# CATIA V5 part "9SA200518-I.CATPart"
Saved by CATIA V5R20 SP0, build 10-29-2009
Part number: 9SA200518-I
Revision: ANY
Definition: UNKNOWN
Nomenclature: 9SA200518-I
Source: Unknown
Bounding box of the stored display mesh (mm): x -5.752 to 5.752, y -16 to 3, z -5.9 to 5.9
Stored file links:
  C:\Users\Utente\Desktop\IO LAVORO\3D X SITO CF\CUMSA\3D files SA\SA 200518\9SA200518-I.CATPart
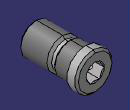
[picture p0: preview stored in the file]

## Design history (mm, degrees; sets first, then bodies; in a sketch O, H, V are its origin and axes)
Body1 "Cortar-Extruir1" (main body)
  Solid1: solid without history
